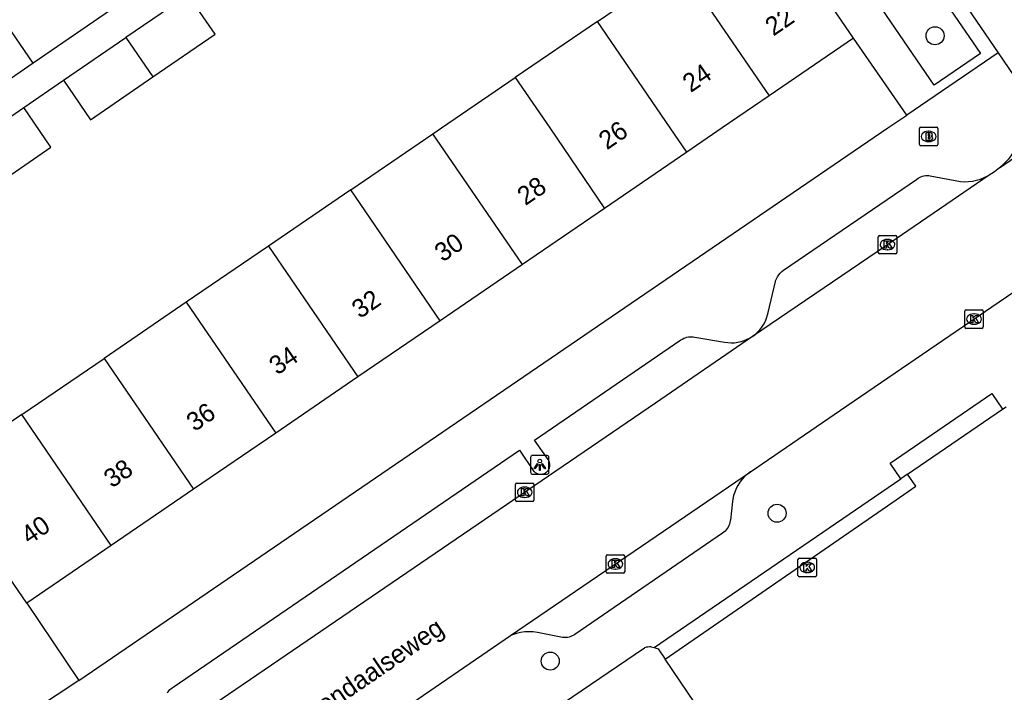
# Model space of a CAD drawing. Extents: x 157466 to 158888, y 383063 to 384677.
# Drawn here: x 158228.2 to 158281.5, y 383719.4 to 383755.9 of the extents above; entities that cross this region are included whole.
import ezdxf

# ---------------------------------------------------------------- set-up
doc = ezdxf.new("R2010")
doc.units = 0
for name, color, linetype in [('IMGEO_Boom', 7, 'Continuous'), ('IMGEO_Brandkraan', 7, 'Continuous'), ('IMGEO_Groenvoorziening', 7, 'Continuous'), ('IMGEO_Kolk', 7, 'Continuous'), ('IMGEO_Lichtpunt', 7, 'Continuous'), ('IMGEO_Openbare_ruimte_label', 7, 'Continuous'), ('IMGEO_Pand', 7, 'Continuous'), ('IMGEO_Pand_nummerreeks', 7, 'Continuous'), ('IMGEO_Parkeervlak_open', 7, 'Continuous'), ('IMGEO_Rijbaan_lokaal_open', 7, 'Continuous'), ('IMGEO_Voetpad_gesloten', 7, 'Continuous'), ('IMGEO_Voetpad_open', 7, 'Continuous')]:
    doc.layers.add(name, color=color, linetype=linetype)

msp = doc.modelspace()

# ---------------------------------------------------------------- linework, layer by layer
at = {"layer": 'IMGEO_Boom'}
for centre in [(158277.8, 383754.993), (158269.25, 383729.141), (158256.968, 383721.134)]:
    msp.add_circle(centre, 0.489, dxfattribs=at)
at = {"layer": 'IMGEO_Brandkraan'}
for p, q in [((158276.956, 383749.115), (158276.956, 383749.967)), ((158277.031, 383750.041), (158277.883, 383750.041)), ((158277.444, 383749.821), (158277.469, 383749.821)), ((158277.957, 383749.967), (158277.957, 383749.115)), ((158277.467, 383749.261), (158277.442, 383749.261)), ((158277.883, 383749.041), (158277.031, 383749.041))]:
    msp.add_line(p, q, dxfattribs=at)
for points in [[(158276.956, 383749.115), (158276.956, 383749.967)], [(158277.031, 383750.041), (158277.883, 383750.041)], [(158277.957, 383749.967), (158277.957, 383749.115)], [(158277.304, 383749.741), (158277.304, 383749.341), (158277.517, 383749.341)], [(158277.535, 383749.741), (158277.304, 383749.741)], [(158277.483, 383749.66), (158277.429, 383749.66), (158277.429, 383749.584)], [(158277.429, 383749.584), (158277.482, 383749.584)], [(158277.491, 383749.508), (158277.429, 383749.508), (158277.429, 383749.427)], [(158277.429, 383749.427), (158277.491, 383749.427)], [(158277.883, 383749.041), (158277.031, 383749.041)]]:
    msp.add_lwpolyline(points, dxfattribs=at)
for centre, radius, start, end in [((158277.033, 383749.965), 0.0765, 91.552, 178.448), ((158277.033, 383749.965), 0.0765, 91.552, 178.448), ((158277.881, 383749.965), 0.0765, 1.552, 88.448), ((158277.881, 383749.965), 0.0765, 1.552, 88.448), ((158277.484, 383749.622), 0.0379, 267.8285, 90.9355), ((158277.492, 383749.467), 0.0404, 269.8759, 90.5077), ((158277.523, 383749.592), 0.251, 268.6676, 293.5347), ((158277.539, 383749.596), 0.145, 59.4692, 91.5367), ((158277.564, 383749.643), 0.0922, 285.5137, 58.1501), ((158277.569, 383749.451), 0.105, 301.3115, 78.989), ((158277.033, 383749.117), 0.0765, 181.552, 268.448), ((158277.033, 383749.117), 0.0765, 181.552, 268.448), ((158277.881, 383749.117), 0.0765, 271.552, 358.448), ((158277.881, 383749.117), 0.0765, 271.552, 358.448)]:
    msp.add_arc(centre, radius, start, end, dxfattribs=at)
for centre, major_axis, ratio, start_param, end_param in [((158277.443, 383749.541), (-0.387, 0.002), 0.722429, 4.712389, 7.853982), ((158277.468, 383749.541), (-0.39, 0.002), 0.717154, 1.570796, 4.712389)]:
    msp.add_ellipse(centre, major_axis=major_axis, ratio=ratio, start_param=start_param, end_param=end_param, dxfattribs=at)
at = {"layer": 'IMGEO_Groenvoorziening'}
msp.add_lwpolyline([(158262.596, 383721.878), (158262.806, 383721.806), (158263.183, 383721.249)], dxfattribs=at)
at = {"layer": 'IMGEO_Kolk'}
for p, q in [((158274.725, 383743.26), (158274.725, 383744.112)), ((158274.8, 383744.186), (158275.652, 383744.186)), ((158275.213, 383743.966), (158275.238, 383743.966)), ((158275.726, 383744.112), (158275.726, 383743.26)), ((158275.236, 383743.406), (158275.211, 383743.406)), ((158275.652, 383743.186), (158274.8, 383743.186)), ((158279.409, 383739.226), (158279.409, 383740.078)), ((158279.484, 383740.152), (158280.336, 383740.152)), ((158279.897, 383739.932), (158279.922, 383739.932)), ((158280.41, 383740.078), (158280.41, 383739.226)), ((158280.336, 383739.152), (158279.484, 383739.152)), ((158279.92, 383739.372), (158279.895, 383739.372)), ((158255.086, 383729.85), (158255.086, 383730.702)), ((158255.161, 383730.776), (158256.013, 383730.776)), ((158256.087, 383730.702), (158256.087, 383729.85)), ((158255.574, 383730.556), (158255.599, 383730.556)), ((158256.013, 383729.776), (158255.161, 383729.776)), ((158255.597, 383729.996), (158255.572, 383729.996)), ((158260.072, 383726.895), (158260.924, 383726.895)), ((158259.997, 383725.969), (158259.997, 383726.821)), ((158260.485, 383726.675), (158260.51, 383726.675)), ((158260.998, 383726.821), (158260.998, 383725.969)), ((158270.379, 383725.779), (158270.379, 383726.631)), ((158270.454, 383726.705), (158271.306, 383726.705)), ((158270.867, 383726.485), (158270.892, 383726.485)), ((158271.38, 383726.631), (158271.38, 383725.779)), ((158260.924, 383725.895), (158260.072, 383725.895)), ((158260.508, 383726.115), (158260.483, 383726.115)), ((158270.89, 383725.925), (158270.865, 383725.925)), ((158271.306, 383725.705), (158270.454, 383725.705))]:
    msp.add_line(p, q, dxfattribs=at)
for points in [[(158274.725, 383743.26), (158274.725, 383744.112)], [(158274.8, 383744.186), (158275.652, 383744.186)], [(158275.726, 383744.112), (158275.726, 383743.26)], [(158275.046, 383743.886), (158275.169, 383743.886), (158275.169, 383743.735), (158275.299, 383743.886), (158275.463, 383743.886), (158275.317, 383743.735), (158275.47, 383743.486), (158275.318, 383743.486), (158275.233, 383743.65), (158275.169, 383743.583), (158275.169, 383743.486), (158275.046, 383743.486), (158275.046, 383743.886)], [(158275.652, 383743.186), (158274.8, 383743.186)], [(158279.409, 383739.226), (158279.409, 383740.078)], [(158279.484, 383740.152), (158280.336, 383740.152)], [(158279.73, 383739.852), (158279.853, 383739.852), (158279.853, 383739.701), (158279.983, 383739.852), (158280.147, 383739.852), (158280.001, 383739.701), (158280.154, 383739.452), (158280.002, 383739.452), (158279.917, 383739.616), (158279.853, 383739.549), (158279.853, 383739.452), (158279.73, 383739.452), (158279.73, 383739.852)], [(158280.41, 383740.078), (158280.41, 383739.226)], [(158280.336, 383739.152), (158279.484, 383739.152)], [(158255.086, 383729.85), (158255.086, 383730.702)], [(158255.161, 383730.776), (158256.013, 383730.776)], [(158256.087, 383730.702), (158256.087, 383729.85)], [(158255.407, 383730.476), (158255.53, 383730.476), (158255.53, 383730.325), (158255.66, 383730.476), (158255.824, 383730.476), (158255.678, 383730.325), (158255.831, 383730.076), (158255.679, 383730.076), (158255.594, 383730.24), (158255.53, 383730.173), (158255.53, 383730.076), (158255.407, 383730.076), (158255.407, 383730.476)], [(158256.013, 383729.776), (158255.161, 383729.776)], [(158260.072, 383726.895), (158260.924, 383726.895)], [(158259.997, 383725.969), (158259.997, 383726.821)], [(158260.318, 383726.595), (158260.441, 383726.595), (158260.441, 383726.444), (158260.571, 383726.595), (158260.735, 383726.595), (158260.589, 383726.444), (158260.742, 383726.195), (158260.59, 383726.195), (158260.505, 383726.359), (158260.441, 383726.292), (158260.441, 383726.195), (158260.318, 383726.195), (158260.318, 383726.595)], [(158260.998, 383726.821), (158260.998, 383725.969)], [(158270.379, 383725.779), (158270.379, 383726.631)], [(158270.454, 383726.705), (158271.306, 383726.705)], [(158270.7, 383726.405), (158270.823, 383726.405), (158270.823, 383726.254), (158270.953, 383726.405), (158271.117, 383726.405), (158270.971, 383726.254), (158271.124, 383726.005), (158270.972, 383726.005), (158270.887, 383726.169), (158270.823, 383726.102), (158270.823, 383726.005), (158270.7, 383726.005), (158270.7, 383726.405)], [(158271.38, 383726.631), (158271.38, 383725.779)], [(158260.924, 383725.895), (158260.072, 383725.895)], [(158271.306, 383725.705), (158270.454, 383725.705)]]:
    msp.add_lwpolyline(points, dxfattribs=at)
for centre, start, end in [((158274.802, 383744.11), 91.552, 178.448), ((158274.802, 383744.11), 91.552, 178.448), ((158275.65, 383744.11), 1.552, 88.448), ((158275.65, 383744.11), 1.552, 88.448), ((158274.802, 383743.262), 181.552, 268.448), ((158274.802, 383743.262), 181.552, 268.448), ((158275.65, 383743.262), 271.552, 358.448), ((158275.65, 383743.262), 271.552, 358.448), ((158279.486, 383740.076), 91.552, 178.448), ((158279.486, 383740.076), 91.552, 178.448), ((158280.334, 383740.076), 1.552, 88.448), ((158280.334, 383740.076), 1.552, 88.448), ((158279.486, 383739.228), 181.552, 268.448), ((158279.486, 383739.228), 181.552, 268.448), ((158280.334, 383739.228), 271.552, 358.448), ((158280.334, 383739.228), 271.552, 358.448), ((158255.163, 383730.7), 91.552, 178.448), ((158255.163, 383730.7), 91.552, 178.448), ((158256.011, 383730.7), 1.552, 88.448), ((158256.011, 383730.7), 1.552, 88.448), ((158255.163, 383729.852), 181.552, 268.448), ((158255.163, 383729.852), 181.552, 268.448), ((158256.011, 383729.852), 271.552, 358.448), ((158256.011, 383729.852), 271.552, 358.448), ((158260.074, 383726.819), 91.552, 178.448), ((158260.074, 383726.819), 91.552, 178.448), ((158260.922, 383726.819), 1.552, 88.448), ((158260.922, 383726.819), 1.552, 88.448), ((158270.456, 383726.629), 91.552, 178.448), ((158270.456, 383726.629), 91.552, 178.448), ((158271.304, 383726.629), 1.552, 88.448), ((158271.304, 383726.629), 1.552, 88.448), ((158260.074, 383725.971), 181.552, 268.448), ((158260.074, 383725.971), 181.552, 268.448), ((158260.922, 383725.971), 271.552, 358.448), ((158260.922, 383725.971), 271.552, 358.448), ((158270.456, 383725.781), 181.552, 268.448), ((158270.456, 383725.781), 181.552, 268.448), ((158271.304, 383725.781), 271.552, 358.448), ((158271.304, 383725.781), 271.552, 358.448)]:
    msp.add_arc(centre, 0.0765, start, end, dxfattribs=at)
for centre, major_axis, ratio, start_param, end_param in [((158275.212, 383743.686), (-0.387, 0.002), 0.722429, 4.712389, 7.853982), ((158275.237, 383743.686), (-0.39, 0.002), 0.717154, 1.570796, 4.712389), ((158279.896, 383739.652), (-0.387, 0.002), 0.722429, 4.712389, 7.853982), ((158279.921, 383739.652), (-0.39, 0.002), 0.717154, 1.570796, 4.712389), ((158255.573, 383730.276), (-0.387, 0.002), 0.722429, 4.712389, 7.853982), ((158255.598, 383730.276), (-0.39, 0.002), 0.717154, 1.570796, 4.712389), ((158260.484, 383726.395), (-0.387, 0.002), 0.722429, 4.712389, 7.853982), ((158260.509, 383726.395), (-0.39, 0.002), 0.717154, 1.570796, 4.712389), ((158270.866, 383726.205), (-0.387, 0.002), 0.722429, 4.712389, 7.853982), ((158270.891, 383726.205), (-0.39, 0.002), 0.717154, 1.570796, 4.712389)]:
    msp.add_ellipse(centre, major_axis=major_axis, ratio=ratio, start_param=start_param, end_param=end_param, dxfattribs=at)
at = {"layer": 'IMGEO_Lichtpunt'}
for p, q in [((158255.904, 383732.166), (158255.904, 383731.359)), ((158255.904, 383732.166), (158255.904, 383731.359)), ((158256.806, 383732.261), (158255.998, 383732.261)), ((158256.806, 383732.261), (158255.998, 383732.261)), ((158256.9, 383731.359), (158256.9, 383732.166)), ((158256.9, 383731.359), (158256.9, 383732.166)), ((158255.998, 383731.265), (158256.806, 383731.265)), ((158255.998, 383731.265), (158256.806, 383731.265))]:
    msp.add_line(p, q, dxfattribs=at)
for points in [[(158256.278, 383731.83), (158256.317, 383731.802), (158256.129, 383731.54), (158256.091, 383731.567), (158256.278, 383731.83)], [(158256.38, 383731.782), (158256.427, 383731.782), (158256.427, 383731.46), (158256.38, 383731.46), (158256.38, 383731.782)], [(158256.49, 383731.802), (158256.528, 383731.829), (158256.715, 383731.567), (158256.676, 383731.539), (158256.49, 383731.802)]]:
    msp.add_lwpolyline(points, dxfattribs=at)
msp.add_circle((158256.403, 383731.964), 0.0994, dxfattribs=at)
for centre, start, end in [((158255.998, 383732.166), 90, 180), ((158255.998, 383732.166), 90, 180), ((158256.806, 383732.166), 0, 90), ((158256.806, 383732.166), 0, 90), ((158255.998, 383731.359), 180, 270), ((158255.998, 383731.359), 180, 270), ((158256.806, 383731.359), 270, 0), ((158256.806, 383731.359), 270, 360)]:
    msp.add_arc(centre, 0.0946, start, end, dxfattribs=at)
at = {"layer": 'IMGEO_Pand'}
for points in [[(158273.392, 383754.863), (158268.557, 383761.942)], [(158259.524, 383755.771), (158263.977, 383758.813)], [(158263.977, 383758.813), (158268.814, 383751.734)], [(158228.983, 383753.512), (158225.877, 383758.036)], [(158237.359, 383757.217), (158233.994, 383754.903)], [(158235.456, 383752.764), (158238.821, 383755.077), (158237.359, 383757.217)], [(158259.524, 383755.771), (158255.072, 383752.729)], [(158264.363, 383748.692), (158263.469, 383750), (158259.524, 383755.771)], [(158230.619, 383752.581), (158233.994, 383754.903)], [(158233.994, 383754.903), (158235.456, 383752.764)], [(158273.392, 383754.863), (158268.814, 383751.734)], [(158228.983, 383753.512), (158225.569, 383751.168), (158223.877, 383750), (158222.525, 383749.067), (158218.397, 383746.244)], [(158230.619, 383752.581), (158232.08, 383750.443), (158235.456, 383752.764)], [(158250.62, 383749.688), (158251.077, 383750), (158255.072, 383752.729)], [(158255.072, 383752.729), (158256.938, 383750), (158259.911, 383745.649)], [(158268.814, 383751.734), (158266.277, 383750), (158264.363, 383748.692)], [(158225.108, 383748.791), (158228.476, 383751.106)], [(158226.568, 383746.655), (158229.936, 383748.97), (158228.476, 383751.106)], [(158246.168, 383746.646), (158250.62, 383749.688)], [(158255.46, 383742.607), (158250.62, 383749.688)], [(158264.363, 383748.692), (158259.911, 383745.649)], [(158246.168, 383746.646), (158241.716, 383743.605)], [(158251.008, 383739.564), (158246.168, 383746.646)], [(158259.911, 383745.649), (158255.46, 383742.607)], [(158241.716, 383743.605), (158237.263, 383740.562)], [(158241.716, 383743.605), (158246.557, 383736.522)], [(158255.46, 383742.607), (158251.008, 383739.564)], [(158237.263, 383740.562), (158232.811, 383737.521)], [(158237.263, 383740.562), (158242.105, 383733.479)], [(158251.008, 383739.564), (158246.557, 383736.522)], [(158228.359, 383734.479), (158232.811, 383737.521)], [(158232.811, 383737.521), (158237.653, 383730.437)], [(158246.557, 383736.522), (158242.105, 383733.479)], [(158228.359, 383734.479), (158223.783, 383731.353)], [(158233.201, 383727.394), (158228.359, 383734.479)], [(158242.105, 383733.479), (158237.653, 383730.437)], [(158228.626, 383724.267), (158223.783, 383731.353)], [(158237.653, 383730.437), (158233.201, 383727.394)], [(158233.201, 383727.394), (158228.626, 383724.267)]]:
    msp.add_lwpolyline(points, dxfattribs=at)
at = {"layer": 'IMGEO_Parkeervlak_open'}
for points in [[(158263.183, 383721.249), (158275.456, 383729.709), (158276.755, 383730.605), (158276.313, 383731.261)], [(158272.403, 383707.609), (158263.183, 383721.249)]]:
    msp.add_lwpolyline(points, dxfattribs=at)
at = {"layer": 'IMGEO_Rijbaan_lokaal_open'}
for points in [[(158276.019, 383760.753), (158276.8, 383760.196), (158277.966, 383758.835), (158280.976, 383754.417), (158281.209, 383754.075)], [(158281.209, 383754.075), (158282.058, 383752.828), (158282.092, 383752.772), (158282.263, 383752.459), (158282.405, 383752.131), (158282.517, 383751.792), (158282.598, 383751.444), (158282.648, 383751.09), (158282.667, 383750.734), (158282.653, 383750.377), (158282.591, 383750), (158282.552, 383749.835), (158282.452, 383749.506), (158282.323, 383749.189), (158282.165, 383748.883), (158281.981, 383748.594), (158281.772, 383748.321), (158281.54, 383748.069), (158281.286, 383747.838)], [(158281.286, 383747.838), (158290.116, 383753.905), (158290.185, 383753.958)], [(158281.286, 383747.838), (158281.012, 383747.631), (158280.721, 383747.449)], [(158280.721, 383747.449), (158274.673, 383743.3), (158267.916, 383738.718)], [(158267.801, 383731.384), (158272.686, 383734.719), (158278.94, 383738.991), (158282.459, 383741.394)], [(158267.916, 383738.718), (158262.66, 383735.101), (158234.944, 383716.183)], [(158254.816, 383722.516), (158267.801, 383731.384)], [(158247.569, 383717.567), (158248.547, 383718.234), (158254.816, 383722.516)]]:
    msp.add_lwpolyline(points, dxfattribs=at)
at = {"layer": 'IMGEO_Voetpad_gesloten'}
for points in [[(158275.946, 383731.01), (158275.37, 383731.852), (158280.874, 383735.617), (158281.45, 383734.775)], [(158276.313, 383731.261), (158281.45, 383734.775)], [(158276.313, 383731.261), (158275.946, 383731.01)]]:
    msp.add_lwpolyline(points, dxfattribs=at)
at = {"layer": 'IMGEO_Voetpad_open'}
for points in [[(158276.62, 383759.361), (158280.256, 383754.037), (158277.76, 383752.323), (158272.324, 383760.284), (158273.854, 383761.334), (158276.62, 383759.361)], [(158235.79, 383758.202), (158228.983, 383753.512)], [(158276.273, 383750.703), (158273.392, 383754.863)], [(158281.209, 383754.075), (158276.273, 383750.703)], [(158228.476, 383751.106), (158230.619, 383752.581)], [(158231.45, 383720.093), (158275.244, 383750), (158276.273, 383750.703)], [(158267.916, 383738.718), (158268.061, 383738.826), (158268.196, 383738.947), (158268.32, 383739.08), (158268.431, 383739.223), (158268.529, 383739.376), (158268.613, 383739.536), (158268.682, 383739.704), (158268.736, 383739.876), (158268.765, 383740.002), (158269.157, 383741.694), (158269.169, 383741.729), (158269.217, 383741.84), (158269.274, 383741.947), (158269.341, 383742.048), (158269.416, 383742.143), (158269.5, 383742.231), (158269.591, 383742.311), (158276.797, 383747.212), (158276.815, 383747.226), (158276.885, 383747.275), (158276.96, 383747.318), (158277.038, 383747.354), (158277.118, 383747.383), (158277.201, 383747.405), (158277.286, 383747.419), (158277.372, 383747.425), (158277.458, 383747.424), (158277.543, 383747.415), (158279.173, 383747.106), (158279.394, 383747.092), (158279.615, 383747.098), (158279.834, 383747.123), (158280.051, 383747.168), (158280.262, 383747.232), (158280.467, 383747.315), (158280.664, 383747.416), (158280.721, 383747.449)], [(158236.237, 383719.41), (158236.278, 383719.474), (158236.324, 383719.534), (158236.375, 383719.59), (158236.431, 383719.642), (158236.492, 383719.688), (158236.556, 383719.728), (158255.304, 383732.556), (158256.079, 383731.408), (158256.111, 383731.377), (158256.147, 383731.349), (158256.184, 383731.324), (158256.224, 383731.302), (158256.265, 383731.284), (158256.308, 383731.27), (158256.351, 383731.26), (158256.396, 383731.253), (158256.441, 383731.251), (158256.486, 383731.253), (158256.531, 383731.259), (158256.575, 383731.268), (158256.618, 383731.282), (158256.659, 383731.299), (158256.699, 383731.32), (158256.737, 383731.345), (158256.772, 383731.373), (158256.805, 383731.403), (158256.835, 383731.437), (158256.862, 383731.473), (158256.885, 383731.512), (158256.905, 383731.552), (158256.921, 383731.594), (158256.934, 383731.637), (158256.942, 383731.682), (158256.947, 383731.726), (158256.947, 383731.771), (158256.944, 383731.816), (158256.936, 383731.861), (158256.925, 383731.904), (158256.91, 383731.947), (158256.891, 383731.987), (158256.868, 383732.026), (158256.857, 383732.043), (158256.121, 383733.101), (158264.041, 383738.523), (158264.119, 383738.573), (158264.196, 383738.613), (158264.276, 383738.645), (158264.359, 383738.671), (158264.444, 383738.689), (158264.53, 383738.699), (158264.617, 383738.701), (158264.703, 383738.696), (158264.789, 383738.683), (158266.402, 383738.406), (158266.58, 383738.38), (158266.76, 383738.37), (158266.94, 383738.376), (158267.119, 383738.398), (158267.295, 383738.436), (158267.467, 383738.489), (158267.634, 383738.558), (158267.793, 383738.641), (158267.916, 383738.718)], [(158281.45, 383734.775), (158281.649, 383734.911)], [(158267.801, 383731.384), (158267.64, 383731.263), (158267.491, 383731.129), (158267.354, 383730.981), (158267.231, 383730.822), (158267.123, 383730.652), (158267.03, 383730.474), (158266.953, 383730.288), (158266.894, 383730.096), (158266.852, 383729.899), (158266.835, 383729.78), (158266.721, 383728.774), (158266.715, 383728.729), (158266.696, 383728.64), (158266.67, 383728.554), (158266.636, 383728.471), (158266.595, 383728.391), (158266.547, 383728.315), (158266.492, 383728.243), (158266.431, 383728.177), (158266.365, 383728.116), (158266.293, 383728.062), (158258.307, 383722.582), (158258.238, 383722.539), (158258.158, 383722.498), (158258.075, 383722.464), (158257.989, 383722.438), (158257.901, 383722.42), (158257.812, 383722.409), (158257.722, 383722.407), (158257.632, 383722.412), (158257.543, 383722.426), (158256.269, 383722.684), (158256.044, 383722.714), (158255.818, 383722.724), (158255.591, 383722.713), (158255.366, 383722.683), (158255.145, 383722.632), (158254.93, 383722.562), (158254.816, 383722.516)], [(158262.596, 383721.878), (158275.946, 383731.01)], [(158228.626, 383724.267), (158231.45, 383720.093)], [(158233.32, 383702.286), (158245.028, 383710.284), (158262.079, 383721.862)], [(158262.44, 383721.901), (158262.596, 383721.878)], [(158231.45, 383720.093), (158227.982, 383717.792)]]:
    msp.add_lwpolyline(points, dxfattribs=at)
msp.add_arc((158262.365, 383720.907), 0.997, 85.6714, 106.6604, dxfattribs=at)

# ---------------------------------------------------------------- texts
at = {"layer": 'IMGEO_Openbare_ruimte_label'}
msp.add_text('Lievendaalseweg', height=1, rotation=34.3256, dxfattribs=at).set_placement((158242.764, 383716.869))
at = {"layer": 'IMGEO_Pand_nummerreeks'}
for s, rotation, p in [('22', 34.3512, (158269.047, 383754.946)), ('24', 34.3512, (158264.573, 383751.888)), ('26', 34.3531, (158260.034, 383748.786)), ('28', 34.3512, (158255.623, 383745.771)), ('30', 34.3512, (158251.146, 383742.711)), ('32', 34.3512, (158246.664, 383739.648)), ('34', 34.3512, (158242.19, 383736.59)), ('36', 34.3512, (158237.713, 383733.53)), ('38', 34.3512, (158233.24, 383730.473)), ('40', 34.3512, (158228.763, 383727.413))]:
    msp.add_text(s, height=1, rotation=rotation, dxfattribs=at).set_placement(p)

doc.saveas('drawing.dxf')
